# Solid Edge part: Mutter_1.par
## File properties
Sűrűség: 0,000 kg/m^3
Pontosság: 0,990
Author: ahadarics
Last saved by: ahadarics
Revision: 76
Username: ahadarics
Dokumentum tartalom típus: 0
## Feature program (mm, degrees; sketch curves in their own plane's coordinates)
base feature "unnamed BaseFeature 1"
thread "unnamed Thread 1"
chamfer "Letörés_1"  SetBackValue2 = 60 deg
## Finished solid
Body 1: solid body, 23 faces, 46 edges, 24 vertices.
  Faces by surface: cone 14, plane 8, cylinder 1
  Edges by curve: spline 24, circle 16, line 6
Bounding box of the edges (mm): 4.000 x 11.547 x 10.000, from (0, -5.7735, -5) to (4, 5.7735, 5).
Cylindrical faces by radius (mm): R2.4585 x1
Conical faces (half-angle, radius in mm at the cone's reference point): 60 deg R2.4585 x1, 60 deg R2.9781 x1, 60 deg R5.3868 x12
Planar faces by outward normal: +x 1, +z 1, -x 1, -z 1, oblique 4
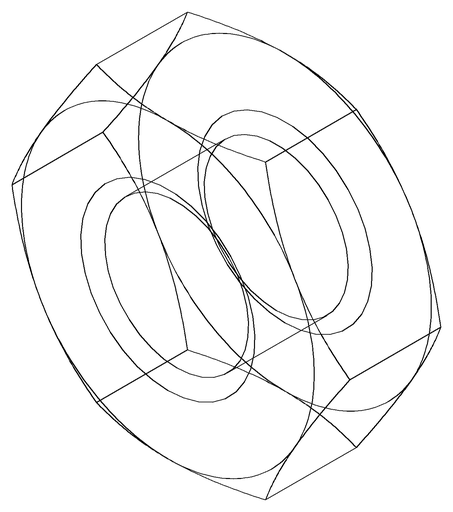
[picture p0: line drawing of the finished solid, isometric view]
